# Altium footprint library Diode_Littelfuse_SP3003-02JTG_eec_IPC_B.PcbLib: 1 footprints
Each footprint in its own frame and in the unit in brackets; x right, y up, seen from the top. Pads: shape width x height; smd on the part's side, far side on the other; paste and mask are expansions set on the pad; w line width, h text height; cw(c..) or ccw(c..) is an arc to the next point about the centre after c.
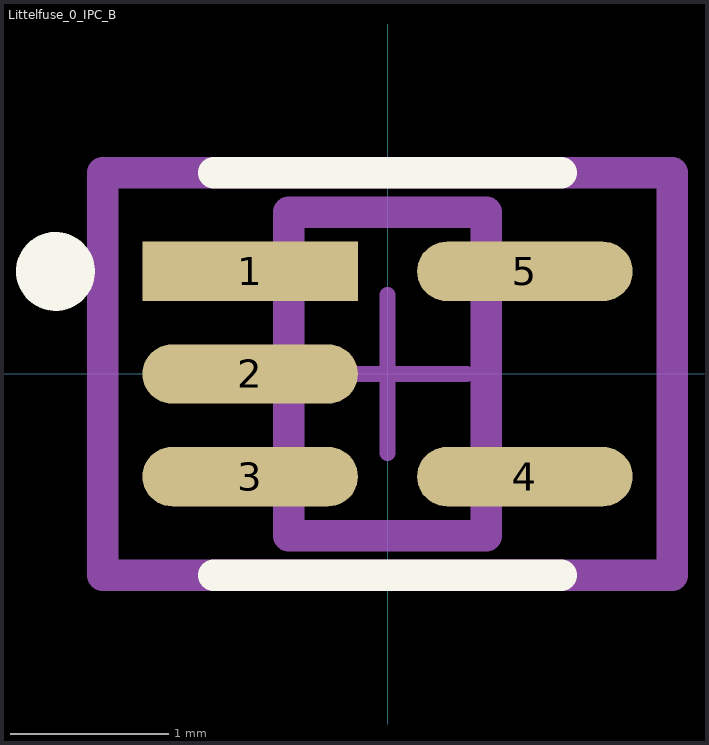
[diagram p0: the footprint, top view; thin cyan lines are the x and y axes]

## Littelfuse_0_IPC_B [mm]
pads (5):
  rect 1.366x0.376 smd paste+0 mask+0: 1(-0.87,0.65)
  rrect100% 1.366x0.376 smd paste+0 mask+0: 2(-0.87,0) 3(-0.87,-0.65) 4(0.87,-0.65) 5(0.87,0.65)
Top Overlay:
  circle w0.25: c-2.103,0.65 r0.125
  lines w0.2: -1.1,-1.275 1.1,-1.275 ; -1.1,1.275 1.1,1.275
Mechanical 10:
  lines w0.2: -1.803,-1.275 1.803,-1.275 1.803,1.275 -1.803,1.275 -1.803,-1.275
  text ".Designator" at 0,0 h1
Mechanical 12:
  lines w0.2: -0.625,-1.025 0.625,-1.025 0.625,1.025 -0.625,1.025 -0.625,-1.025
Mechanical 15:
  lines w0.1: -0.5,0 0.5,0 ; 0,-0.5 0,0.5
  lines w0.2: -1.803,-1.275 1.803,-1.275 1.803,1.275 -1.803,1.275 -1.803,-1.275
3D body "Diode_Littelfuse_SP3003-02JTG_eec.STEP": height 0.25, standoff 0, extent -1.803,-1.275 1.803,1.275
